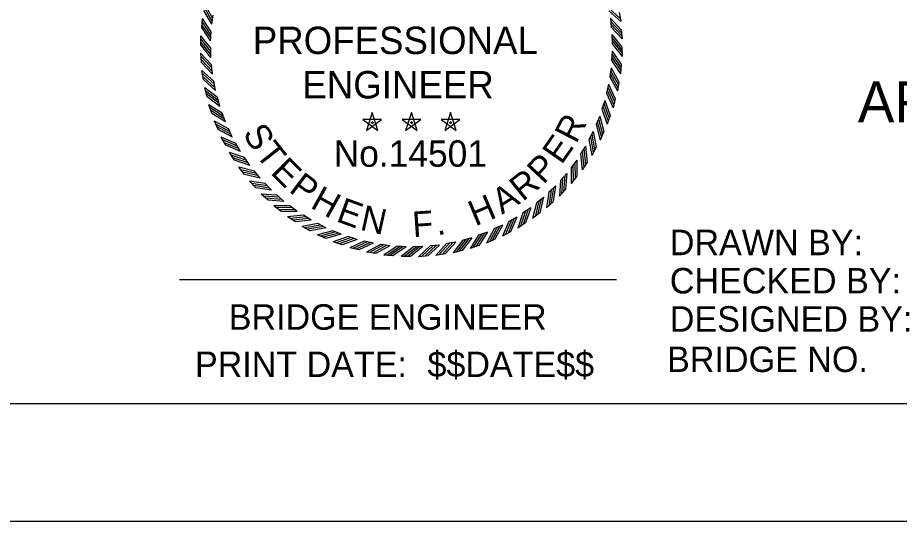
# Model space of a CAD drawing. Extents: x 16 to 1228740, y 11 to 152440.
# Drawn here: x 17.6145 to 17.9747, y 10.7095 to 10.9152 of the extents above; entities that cross this region are included whole.
import ezdxf

# ---------------------------------------------------------------- set-up
doc = ezdxf.new("R2010")
doc.units = 0
for name, color, linetype in [('B_border', 7, 'Continuous'), ('B_Print_Date_Text', 7, 'Continuous'), ('B_Text', 7, 'Continuous'), ('B_Title Text', 7, 'Continuous'), ('R_Border', 7, 'Continuous'), ('STAMP_FRED', 7, 'Continuous')]:
    doc.layers.add(name, color=color, linetype=linetype)

msp = doc.modelspace()

# ---------------------------------------------------------------- linework, layer by layer
at = {"layer": 'B_border'}
msp.add_line((17.68061, 10.80825), (17.85911, 10.80825), dxfattribs=at)
msp.add_line((17.68061, 10.80825), (17.85911, 10.80825), dxfattribs=at)
at = {"layer": 'R_Border'}
msp.add_line((18.44221, 10.75755), (15.78327, 10.75755), dxfattribs=at)
msp.add_lwpolyline([(15.65694, 12.54282), (18.49027, 12.54282), (18.49027, 10.70949), (15.65694, 10.70949)], close=True, dxfattribs=at)
at = {"layer": 'STAMP_FRED'}
for p, q in [((17.69379, 10.91249), (17.69438, 10.91622)), ((17.86024, 10.91733), (17.8609, 10.91362)), ((17.68972, 10.91115), (17.68999, 10.91491)), ((17.85662, 10.91503), (17.85697, 10.91127)), ((17.69334, 10.90573), (17.69362, 10.90949)), ((17.85728, 10.90828), (17.85732, 10.9045)), ((17.86109, 10.91028), (17.86143, 10.90652)), ((17.68939, 10.90405), (17.68935, 10.90782)), ((17.69345, 10.89894), (17.69341, 10.90272)), ((17.85739, 10.9015), (17.85711, 10.89773)), ((17.86134, 10.90317), (17.86138, 10.8994)), ((17.68964, 10.89695), (17.6893, 10.9007)), ((17.69411, 10.8922), (17.69376, 10.89596)), ((17.85694, 10.89473), (17.85635, 10.891)), ((17.86101, 10.89608), (17.86074, 10.89232)), ((17.69049, 10.88989), (17.68983, 10.89361)), ((17.69533, 10.88552), (17.69467, 10.88925)), ((17.85592, 10.88803), (17.85503, 10.88436)), ((17.8601, 10.88903), (17.85951, 10.8853)), ((17.69191, 10.88293), (17.69095, 10.88658)), ((17.6939, 10.87611), (17.69265, 10.87966)), ((17.6971, 10.87898), (17.69614, 10.88263)), ((17.85436, 10.88143), (17.85317, 10.87784)), ((17.8586, 10.88208), (17.85771, 10.87842)), ((17.6994, 10.8726), (17.69814, 10.87616)), ((17.75937, 10.87642), (17.75701, 10.86918)), ((17.76172, 10.86918), (17.75937, 10.87642)), ((17.77536, 10.87642), (17.773, 10.86918)), ((17.77771, 10.86918), (17.77536, 10.87642)), ((17.79135, 10.87642), (17.78899, 10.86918)), ((17.7937, 10.86918), (17.79135, 10.87642)), ((17.69645, 10.86948), (17.69491, 10.87292)), ((17.76317, 10.87365), (17.75556, 10.87366)), ((17.75557, 10.87365), (17.76172, 10.86917)), ((17.75702, 10.86918), (17.76318, 10.87365)), ((17.75883, 10.87244), (17.75996, 10.87244)), ((17.75937, 10.87284), (17.75937, 10.87189)), ((17.77916, 10.87365), (17.77155, 10.87366)), ((17.77156, 10.87365), (17.77771, 10.86917)), ((17.77301, 10.86918), (17.77917, 10.87365)), ((17.77482, 10.87244), (17.77595, 10.87244)), ((17.77536, 10.87284), (17.77536, 10.87189)), ((17.79515, 10.87365), (17.78754, 10.87366)), ((17.78755, 10.87365), (17.7937, 10.86917)), ((17.789, 10.86918), (17.79516, 10.87365)), ((17.79081, 10.87244), (17.79194, 10.87244)), ((17.79136, 10.87284), (17.79136, 10.87189)), ((17.85226, 10.87498), (17.85077, 10.87151)), ((17.85654, 10.87528), (17.85535, 10.8717)), ((17.70222, 10.86643), (17.70067, 10.86988)), ((17.84963, 10.86873), (17.84787, 10.86539)), ((17.85393, 10.86867), (17.85244, 10.86521)), ((17.69954, 10.86308), (17.69772, 10.86638)), ((17.70554, 10.86052), (17.70371, 10.86382)), ((17.8465, 10.86272), (17.84446, 10.85953)), ((17.85077, 10.86231), (17.84901, 10.85897)), ((17.70315, 10.85695), (17.70106, 10.86009)), ((17.70934, 10.8549), (17.70724, 10.85804)), ((17.84288, 10.85698), (17.84059, 10.85398)), ((17.8471, 10.85622), (17.84507, 10.85305)), ((17.70725, 10.85115), (17.7049, 10.8541)), ((17.71359, 10.84961), (17.71124, 10.85257)), ((17.8388, 10.85157), (17.83626, 10.84876)), ((17.71181, 10.8457), (17.70923, 10.84845)), ((17.71826, 10.8447), (17.71567, 10.84745)), ((17.84294, 10.85046), (17.84066, 10.84746)), ((17.83428, 10.8465), (17.83153, 10.84392)), ((17.83832, 10.84506), (17.8358, 10.84226)), ((17.71681, 10.84065), (17.71401, 10.84318)), ((17.72332, 10.84018), (17.72051, 10.84271)), ((17.82937, 10.84183), (17.8264, 10.83949)), ((17.83327, 10.84006), (17.83052, 10.83748)), ((17.72221, 10.83603), (17.71921, 10.83832)), ((17.72873, 10.8361), (17.72573, 10.83839)), ((17.82408, 10.83759), (17.82094, 10.83549)), ((17.72797, 10.83187), (17.7248, 10.83391)), ((17.73447, 10.83248), (17.73129, 10.83452)), ((17.81846, 10.83379), (17.81515, 10.83196)), ((17.82783, 10.83549), (17.82487, 10.83315)), ((17.73406, 10.82821), (17.73073, 10.82997)), ((17.74048, 10.82934), (17.73714, 10.83111)), ((17.81255, 10.83047), (17.8091, 10.82892)), ((17.82202, 10.83139), (17.81889, 10.8293)), ((17.74043, 10.82505), (17.73696, 10.82653)), ((17.74673, 10.82672), (17.74326, 10.8282)), ((17.75318, 10.82462), (17.7496, 10.82581)), ((17.80638, 10.82765), (17.80282, 10.82639)), ((17.8159, 10.82779), (17.8126, 10.82596)), ((17.74703, 10.82244), (17.74346, 10.82363)), ((17.75978, 10.82305), (17.75611, 10.82395)), ((17.76649, 10.82204), (17.76275, 10.82263)), ((17.77325, 10.82159), (17.76948, 10.82186)), ((17.78678, 10.82236), (17.78302, 10.82201)), ((17.79345, 10.82358), (17.78973, 10.82292)), ((17.8, 10.82535), (17.79635, 10.82438)), ((17.80287, 10.82215), (17.79931, 10.82089)), ((17.8095, 10.8247), (17.80606, 10.82315)), ((17.75383, 10.82037), (17.75017, 10.82126)), ((17.76078, 10.81888), (17.75706, 10.81947)), ((17.76783, 10.81796), (17.76407, 10.81824)), ((17.78003, 10.82169), (17.77626, 10.82166)), ((17.78908, 10.81873), (17.78537, 10.81808)), ((17.79605, 10.82016), (17.7924, 10.8192)), ((17.77493, 10.81763), (17.77116, 10.8176)), ((17.78203, 10.81789), (17.77827, 10.81755))]:
    msp.add_line(p, q, dxfattribs=at)
for points in [[(17.694, 10.91368), (17.69083, 10.91939)], [(17.69417, 10.91498), (17.69101, 10.92069)], [(17.85585, 10.91922), (17.86069, 10.91486)], [(17.6938, 10.91249), (17.69063, 10.91819)], [(17.85606, 10.91799), (17.8609, 10.91362)], [(17.69344, 10.90693), (17.68982, 10.91235)], [(17.69351, 10.90824), (17.68989, 10.91366)], [(17.69361, 10.90949), (17.68999, 10.91491)], [(17.85662, 10.91503), (17.86108, 10.91028)], [(17.85672, 10.91383), (17.86118, 10.90907)], [(17.85686, 10.91252), (17.86133, 10.90777)], [(17.69334, 10.90572), (17.68972, 10.91114)], [(17.85697, 10.91127), (17.86143, 10.90652)], [(17.85728, 10.90829), (17.86134, 10.90318)], [(17.69341, 10.90272), (17.68935, 10.90782)], [(17.69341, 10.90146), (17.68935, 10.90657)], [(17.69345, 10.90015), (17.68939, 10.90526)], [(17.85728, 10.90707), (17.86134, 10.90197)], [(17.85732, 10.90576), (17.86138, 10.90066)], [(17.69345, 10.89894), (17.68939, 10.90405)], [(17.85732, 10.90451), (17.86138, 10.8994)], [(17.85739, 10.90151), (17.86101, 10.89608)], [(17.69376, 10.89595), (17.68929, 10.90071)], [(17.69387, 10.8947), (17.6894, 10.89946)], [(17.69401, 10.8934), (17.68955, 10.89815)], [(17.85712, 10.89774), (17.86074, 10.89231)], [(17.85722, 10.89899), (17.86084, 10.89356)], [(17.85729, 10.9003), (17.86091, 10.89487)], [(17.69411, 10.89219), (17.68965, 10.89695)], [(17.85693, 10.89474), (17.8601, 10.88903)], [(17.69467, 10.88924), (17.68983, 10.89361)], [(17.69488, 10.888), (17.69004, 10.89237)], [(17.69514, 10.88672), (17.69029, 10.89109)], [(17.85635, 10.89101), (17.85951, 10.8853)], [(17.85656, 10.89224), (17.85972, 10.88654)], [(17.85673, 10.89354), (17.8599, 10.88784)], [(17.69533, 10.88552), (17.69049, 10.88989)], [(17.85562, 10.88686), (17.8583, 10.88091)], [(17.85592, 10.88803), (17.8586, 10.88209)], [(17.69614, 10.88263), (17.69095, 10.88658)], [(17.69644, 10.88141), (17.69126, 10.88536)], [(17.6968, 10.88015), (17.69162, 10.8841)], [(17.85503, 10.88436), (17.85771, 10.87841)], [(17.85534, 10.88558), (17.85802, 10.87963)], [(17.6971, 10.87897), (17.69191, 10.88293)], [(17.69814, 10.87616), (17.69264, 10.87967)], [(17.85397, 10.88029), (17.85615, 10.87414)], [(17.85436, 10.88143), (17.85654, 10.87529)], [(17.69855, 10.87497), (17.69305, 10.87848)], [(17.69901, 10.87374), (17.69351, 10.87725)], [(17.6994, 10.8726), (17.69391, 10.87611)], [(17.85317, 10.87785), (17.85535, 10.8717)], [(17.85358, 10.87904), (17.85576, 10.87289)], [(17.70067, 10.86987), (17.6949, 10.87292)], [(17.85128, 10.87266), (17.85295, 10.86635)], [(17.85177, 10.87388), (17.85344, 10.86757)], [(17.85226, 10.87499), (17.85392, 10.86868)], [(17.70117, 10.86872), (17.69541, 10.87177)], [(17.70174, 10.86754), (17.69597, 10.87059)], [(17.70223, 10.86643), (17.69646, 10.86947)], [(17.84963, 10.86874), (17.85077, 10.86231)], [(17.85078, 10.87151), (17.85244, 10.8652)], [(17.70371, 10.86382), (17.69771, 10.86638)], [(17.70431, 10.86271), (17.69831, 10.86527)], [(17.84787, 10.86539), (17.84901, 10.85897)], [(17.84847, 10.8665), (17.84961, 10.86007)], [(17.84905, 10.86767), (17.85019, 10.86125)], [(17.70497, 10.86158), (17.69897, 10.86414)], [(17.70555, 10.86052), (17.69955, 10.86307)], [(17.84583, 10.86171), (17.84644, 10.85521)], [(17.8465, 10.86272), (17.8471, 10.85623)], [(17.70724, 10.85804), (17.70105, 10.86009)], [(17.70793, 10.85699), (17.70174, 10.85904)], [(17.70868, 10.85591), (17.70249, 10.85797)], [(17.84447, 10.85954), (17.84507, 10.85304)], [(17.84515, 10.86059), (17.84576, 10.85409)], [(17.70934, 10.8549), (17.70315, 10.85695)], [(17.84136, 10.85497), (17.84143, 10.84845)], [(17.84213, 10.85603), (17.8422, 10.84951)], [(17.84288, 10.85699), (17.84295, 10.85046)], [(17.71124, 10.85257), (17.7049, 10.8541)], [(17.71201, 10.85158), (17.70567, 10.85311)], [(17.71285, 10.85057), (17.70651, 10.85211)], [(17.71359, 10.84961), (17.70725, 10.85115)], [(17.83798, 10.85068), (17.8375, 10.84417)], [(17.8388, 10.85157), (17.83833, 10.84506)], [(17.84059, 10.85398), (17.84066, 10.84746)], [(17.71567, 10.84745), (17.70923, 10.84845)], [(17.71652, 10.84652), (17.71008, 10.84753)], [(17.83627, 10.84876), (17.8358, 10.84226)], [(17.83712, 10.84969), (17.83665, 10.84318)], [(17.71744, 10.84559), (17.711, 10.8466)], [(17.71826, 10.84469), (17.71182, 10.8457)], [(17.83153, 10.84392), (17.83052, 10.83748)], [(17.83246, 10.84477), (17.83145, 10.83833)], [(17.83339, 10.84569), (17.83238, 10.83924)], [(17.83428, 10.84651), (17.83328, 10.84007)], [(17.72051, 10.84271), (17.71401, 10.84318)], [(17.72144, 10.84186), (17.71493, 10.84233)], [(17.72243, 10.841), (17.71592, 10.84147)], [(17.72332, 10.84018), (17.71682, 10.84065)], [(17.8274, 10.84026), (17.82586, 10.83392)], [(17.82841, 10.84109), (17.82687, 10.83476)], [(17.82937, 10.84184), (17.82783, 10.8355)], [(17.72573, 10.83839), (17.71921, 10.83832)], [(17.72672, 10.83762), (17.7202, 10.83755)], [(17.72778, 10.83684), (17.72126, 10.83678)], [(17.82307, 10.83693), (17.82101, 10.83074)], [(17.82408, 10.83759), (17.82203, 10.8314)], [(17.82641, 10.83949), (17.82487, 10.83315)], [(17.72874, 10.8361), (17.72222, 10.83603)], [(17.73129, 10.83451), (17.72479, 10.83391)], [(17.73234, 10.83382), (17.72584, 10.83322)], [(17.73346, 10.83314), (17.72696, 10.83254)], [(17.8174, 10.83322), (17.81484, 10.82722)], [(17.81846, 10.83379), (17.8159, 10.82779)], [(17.82094, 10.83549), (17.81889, 10.8293)], [(17.82199, 10.83618), (17.81994, 10.82999)], [(17.73447, 10.83248), (17.72798, 10.83187)], [(17.73714, 10.83111), (17.73072, 10.82997)], [(17.73825, 10.83051), (17.73183, 10.82937)], [(17.73942, 10.82992), (17.733, 10.82878)], [(17.74049, 10.82935), (17.73406, 10.82821)], [(17.81026, 10.82942), (17.80721, 10.82365)], [(17.81144, 10.82999), (17.80839, 10.82422)], [(17.81255, 10.83047), (17.8095, 10.82471)], [(17.81516, 10.83196), (17.8126, 10.82596)], [(17.81626, 10.83256), (17.8137, 10.82656)], [(17.74326, 10.8282), (17.73696, 10.82653)], [(17.74441, 10.82769), (17.73811, 10.82603)], [(17.74563, 10.82721), (17.73932, 10.82554)], [(17.74674, 10.82672), (17.74043, 10.82505)], [(17.7496, 10.82581), (17.74345, 10.82363)], [(17.75079, 10.8254), (17.74464, 10.82322)], [(17.80282, 10.82639), (17.79931, 10.82089)], [(17.80401, 10.82679), (17.8005, 10.8213)], [(17.80524, 10.82726), (17.80172, 10.82176)], [(17.80638, 10.82765), (17.80287, 10.82216)], [(17.80911, 10.82892), (17.80606, 10.82315)], [(17.75204, 10.82501), (17.74589, 10.82283)], [(17.75319, 10.82462), (17.74704, 10.82244)], [(17.75611, 10.82394), (17.75017, 10.82126)], [(17.75733, 10.82364), (17.75138, 10.82095)], [(17.75861, 10.82335), (17.75266, 10.82067)], [(17.75979, 10.82306), (17.75384, 10.82038)], [(17.76276, 10.82263), (17.75705, 10.81946)], [(17.764, 10.82242), (17.75829, 10.81926)], [(17.76529, 10.82224), (17.75959, 10.81908)], [(17.76649, 10.82204), (17.76079, 10.81888)], [(17.76949, 10.82186), (17.76406, 10.81824)], [(17.78302, 10.82201), (17.77827, 10.81754)], [(17.78428, 10.82211), (17.77952, 10.81765)], [(17.78558, 10.82226), (17.78082, 10.8178)], [(17.78679, 10.82236), (17.78203, 10.8179)], [(17.78974, 10.82292), (17.78537, 10.81808)], [(17.79098, 10.82313), (17.78661, 10.81828)], [(17.79226, 10.82338), (17.78789, 10.81854)], [(17.79346, 10.82358), (17.78909, 10.81874)], [(17.79635, 10.82438), (17.7924, 10.8192)], [(17.79757, 10.82469), (17.79362, 10.8195)], [(17.79883, 10.82505), (17.79487, 10.81986)], [(17.8, 10.82535), (17.79605, 10.82016)], [(17.77074, 10.82176), (17.76532, 10.81813)], [(17.77205, 10.82169), (17.76662, 10.81807)], [(17.77326, 10.82159), (17.76783, 10.81797)], [(17.77626, 10.82166), (17.77115, 10.8176)], [(17.77752, 10.82166), (17.77241, 10.8176)], [(17.77882, 10.8217), (17.77372, 10.81764)], [(17.78004, 10.8217), (17.77493, 10.81764)]]:
    msp.add_lwpolyline(points, dxfattribs=at)

# ---------------------------------------------------------------- texts
at = {"layer": 'B_Print_Date_Text'}
msp.add_text('PRINT DATE:', height=0.0104, dxfattribs=at).set_placement((17.68698, 10.76845))
msp.add_text('$$DATE$$', height=0.0104, rotation=359.9999, dxfattribs=at).set_placement((17.78195, 10.76845))
at = {"layer": 'B_Text'}
for s, height, p in [('DRAWN BY:', 0.010417, (17.88091, 10.8182)), ('CHECKED BY:', 0.0104166, (17.88091, 10.80257)), ('BRIDGE ENGINEER', 0.0104, (17.70078, 10.78775)), ('DESIGNED BY:', 0.0104166, (17.88091, 10.78695)), ('BRIDGE NO.', 0.010417, (17.87978, 10.77048))]:
    msp.add_text(s, height=height, dxfattribs=at).set_placement(p)
at = {"layer": 'B_Title Text'}
msp.add_text('ARKANSAS STATE HIGHWAY COMMISSION', height=0.0167, dxfattribs=at).set_placement((17.95772, 10.8725))
at = {"layer": 'STAMP_FRED'}
for s, height, p in [('PROFESSIONAL', 0.0111934, (17.71058, 10.90034)), ('ENGINEER', 0.011193, (17.73083, 10.88221)), ('No.14501', 0.010794, (17.74363, 10.85431))]:
    msp.add_text(s, height=height, dxfattribs=at).set_placement(p)
for s, rotation, p in [('R', 62.6418, (17.84264, 10.8634)), ('S', 300.7985, (17.70627, 10.86797)), ('T', 308.0945, (17.71136, 10.85944)), ('E', 54.981, (17.83668, 10.85484)), ('E', 315.3905, (17.71749, 10.85163)), ('P', 46.9554, (17.82928, 10.8468)), ('P', 323.0513, (17.72494, 10.84433)), ('R', 38.9298, (17.82082, 10.83988)), ('H', 331.0769, (17.73371, 10.83781)), ('A', 31.6338, (17.81237, 10.83467)), ('E', 339.8321, (17.74422, 10.83219)), ('H', 22.8786, (17.80145, 10.8299)), ('N', 347.4929, (17.75402, 10.82862)), ('F', 3.9089, (17.77609, 10.82554)), ('.', 11.205, (17.786, 10.82622))]:
    msp.add_text(s, height=0.01042, rotation=rotation, dxfattribs=at).set_placement(p)

doc.saveas('drawing.dxf')
